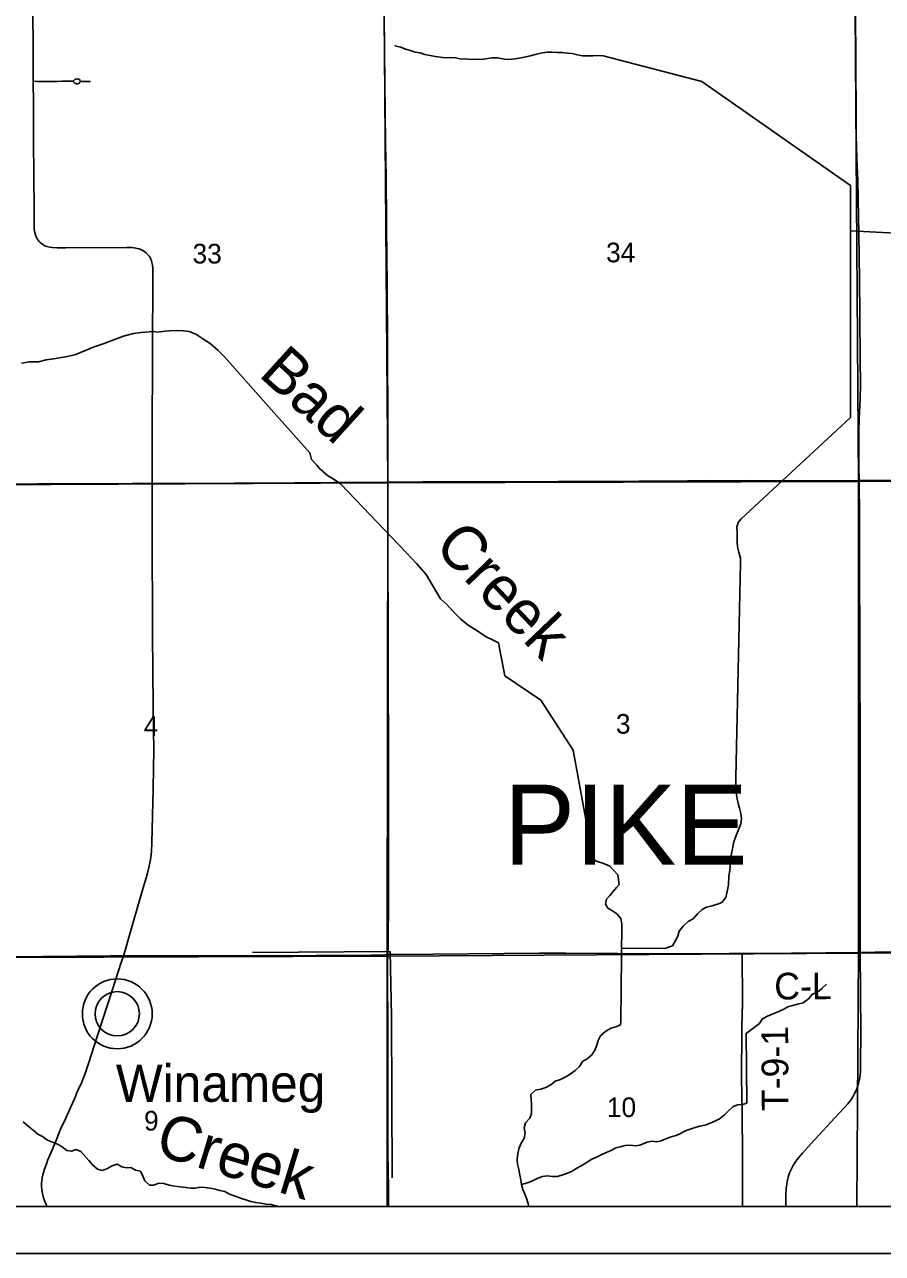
# Model space of a CAD drawing. Extents: x 0 to 34, y 0 to 22.
# Drawn here: x 3.736 to 5.564, y 14 to 16.618 of the extents above; entities that cross this region are included whole.
import ezdxf

# ---------------------------------------------------------------- set-up
doc = ezdxf.new("R2010")
doc.units = 0
for name, color, linetype in [('Default', 7, 'Continuous'), ('GM_X_County_Road', 7, 'Continuous'), ('GM_X_County_Road_Text', 7, 'Continuous'), ('GM_X_Minor_River', 7, 'Continuous'), ('GM_X_Minor_River_Text', 7, 'Continuous'), ('GM_X_Section', 7, 'Continuous'), ('GM_X_Section_Text', 7, 'Continuous'), ('GM_X_State_Route', 7, 'Continuous'), ('GM_X_Township_Road', 7, 'Continuous'), ('GM_X_Township_Road_Text', 7, 'Continuous'), ('GM_X_Township_Text', 7, 'Continuous'), ('GM_X_Unincorporated', 7, 'Continuous'), ('GM_X_Unincorporated_Location', 7, 'Continuous'), ('GM_X_Unincorporated_Text', 7, 'Continuous'), ('SH_Cut_Line', 7, 'Continuous'), ('SH_Data', 7, 'Continuous')]:
    doc.layers.add(name, color=color, linetype=linetype)

msp = doc.modelspace()

# ---------------------------------------------------------------- linework, layer by layer
at = {"layer": 'Default'}
msp.add_lwpolyline([(2.1, 16.6348), (2.1, 14.1), (7.5225, 14.1), (7.5244, 14.8701), (7.5216, 15.6399), (7.5206, 15.6813), (7.5192, 15.8554), (7.5184, 15.927), (7.5171, 16.0545), (7.5165, 16.1851), (7.5145, 16.4463), (7.5138, 16.5271), (7.5134, 16.6254)], dxfattribs=at)
for points in [[(3.5024, 14.1), (4.5087, 14.1), (4.5085, 14.6335), (3.5022, 14.6297)], [(4.5087, 14.1), (5.5091, 14.1), (5.5125, 14.6396), (4.5085, 14.6335)], [(5.5091, 14.1), (6.5139, 14.1), (6.5138, 14.6401), (5.5125, 14.6396)]]:
    msp.add_lwpolyline(points, close=True, dxfattribs=at)
at = {"layer": 'GM_X_County_Road'}
for points in [[(3.7551, 16.4968), (3.7546, 16.5669), (3.7543, 16.6471)], [(3.7637, 16.1607), (3.7614, 16.1652), (3.7595, 16.1697), (3.7581, 16.1751), (3.7572, 16.1819), (3.7568, 16.1939), (3.7567, 16.2342), (3.7564, 16.284), (3.7557, 16.3835), (3.7554, 16.4488), (3.7551, 16.4968)], [(3.7637, 16.1607), (3.7666, 16.1566), (3.7687, 16.1544), (3.7734, 16.1504), (3.7759, 16.1487), (3.7785, 16.1472), (3.7813, 16.146), (3.7842, 16.1451), (3.7901, 16.1437), (3.7963, 16.1429), (3.8056, 16.1423), (3.8243, 16.142), (3.9525, 16.1427), (3.9649, 16.1425), (3.9732, 16.1414), (3.9802, 16.1402), (3.9869, 16.1373), (3.9898, 16.1355), (3.9953, 16.1317)], [(4.0081, 15.6399), (4.0081, 15.6515), (4.0079, 15.6763), (4.008, 15.6981), (4.0084, 15.7229), (4.0082, 15.7416), (4.0096, 16.0896), (4.0095, 16.0989), (4.0089, 16.1051), (4.0077, 16.1112), (4.0068, 16.1142), (4.0057, 16.1171), (4.0038, 16.1214), (4.0016, 16.1247), (3.9953, 16.1317)], [(3.5073, 15.6383), (3.515, 15.6382), (3.5989, 15.6388), (3.6297, 15.6388), (3.6794, 15.639), (3.7261, 15.639), (3.7634, 15.6393), (3.8007, 15.6393), (3.8287, 15.6395), (3.8908, 15.6397), (3.9188, 15.6396), (3.9655, 15.6399), (4.0059, 15.6398), (4.0081, 15.6399)], [(3.9471, 14.6339), (3.95, 14.6431), (3.9671, 14.7028), (3.9872, 14.7714), (3.9976, 14.8072), (4.0014, 14.8223), (4.0039, 14.8346), (4.0052, 14.8438), (4.0065, 14.8562), (4.0075, 14.8749), (4.0106, 14.9899), (4.0114, 15.0334), (4.0115, 15.0738), (4.011, 15.1142), (4.0095, 15.2322), (4.0089, 15.3286), (4.008, 15.5368), (4.0083, 15.5584), (4.0081, 15.5738), (4.0079, 15.6111), (4.0081, 15.6297), (4.0081, 15.6399)], [(4.0081, 15.6399), (4.0276, 15.6402), (4.1053, 15.6404), (4.183, 15.641), (4.3105, 15.6418), (4.3509, 15.6418), (4.3944, 15.6423), (4.4442, 15.6424), (4.5101, 15.6428)], [(4.5101, 15.6428), (4.5841, 15.6433), (4.6742, 15.6436), (4.7147, 15.6438), (4.8732, 15.6446), (4.9354, 15.6447), (5.0442, 15.6452), (5.1002, 15.6453), (5.1966, 15.6463), (5.2401, 15.646), (5.2774, 15.6462), (5.3707, 15.646), (5.4359, 15.6459), (5.4795, 15.6461), (5.5139, 15.6462)], [(5.5139, 15.6462), (5.5634, 15.6462), (5.6256, 15.6465), (5.6629, 15.6464), (5.7531, 15.6465), (5.8526, 15.6468), (5.9178, 15.647), (6.1697, 15.6475), (6.2288, 15.6478), (6.3469, 15.6481), (6.4649, 15.6475), (6.5173, 15.6474)], [(3.5083, 14.6304), (3.5237, 14.6305), (3.531, 14.6306), (3.6305, 14.6314), (3.9195, 14.634), (3.9471, 14.6339)], [(3.7845, 14.1), (3.7824, 14.1044), (3.7788, 14.1129), (3.7768, 14.1187), (3.7752, 14.1247), (3.774, 14.1307), (3.7731, 14.1368), (3.7727, 14.1429), (3.7727, 14.1491), (3.7731, 14.1552), (3.7738, 14.1613), (3.7751, 14.1673), (3.7787, 14.1793), (3.7839, 14.1932), (3.7852, 14.198), (3.7902, 14.209), (3.7963, 14.2223), (3.8046, 14.2429), (3.8146, 14.2681), (3.8206, 14.2803), (3.845, 14.3346), (3.8473, 14.3405), (3.8521, 14.3517), (3.8575, 14.363), (3.8598, 14.3689), (3.8653, 14.3833), (3.8734, 14.4067), (3.8907, 14.4599), (3.9229, 14.5604), (3.9425, 14.6194), (3.9471, 14.6339)], [(3.9471, 14.6339), (4.0283, 14.6336), (4.3578, 14.6345), (4.4448, 14.6349), (4.5039, 14.6364), (4.5103, 14.6365)], [(4.5103, 14.6365), (4.6065, 14.6377), (4.8334, 14.6394), (4.8893, 14.6394), (5.1101, 14.6384), (5.2375, 14.639), (5.2647, 14.639)], [(5.2647, 14.639), (5.2966, 14.6389), (5.5165, 14.641)], [(5.5165, 14.641), (5.548, 14.6414), (5.7625, 14.643), (5.9428, 14.6444), (5.9553, 14.6451), (5.9616, 14.6465), (5.9645, 14.6477), (5.9667, 14.649)]]:
    msp.add_lwpolyline(points, dxfattribs=at)
at = {"layer": 'GM_X_Minor_River'}
for p, q in [((5.2514, 15.013), (5.2615, 15.4713)), ((5.0082, 14.6496), (5.1025, 14.6502))]:
    msp.add_line(p, q, dxfattribs=at)
for points in [[(4.9689, 16.551), (4.9564, 16.5519), (4.9465, 16.5513), (4.9367, 16.5514), (4.9249, 16.5511), (4.9139, 16.5535), (4.9026, 16.5559), (4.8927, 16.5567), (4.8814, 16.558), (4.8708, 16.5585), (4.8598, 16.559), (4.8492, 16.5591), (4.8397, 16.5576), (4.8271, 16.5547), (4.8138, 16.5514), (4.8043, 16.5489), (4.7941, 16.5467), (4.7804, 16.5449), (4.7682, 16.5432), (4.7584, 16.544), (4.7436, 16.5468), (4.7315, 16.5469), (4.7186, 16.5448), (4.7091, 16.5434), (4.6974, 16.5442), (4.6879, 16.5432), (4.6761, 16.5448), (4.6667, 16.5438), (4.6553, 16.5466), (4.6436, 16.5478), (4.6329, 16.5468), (4.6216, 16.5484), (4.6118, 16.55), (4.6, 16.552), (4.5891, 16.554), (4.5789, 16.5572), (4.5686, 16.5588), (4.5581, 16.5627), (4.5479, 16.5654), (4.5381, 16.5697), (4.5275, 16.5717), (4.526, 16.5736)], [(5.2622, 15.5642), (5.4959, 15.7808), (5.4958, 16.2749), (5.1791, 16.4966), (4.9689, 16.551)], [(5.4958, 16.1786), (5.8099, 16.1617), (5.8134, 16.1382), (5.9544, 16.136)], [(3.7302, 15.8965), (3.7462, 15.899), (3.7659, 15.8996), (3.7822, 15.9032), (3.7982, 15.9057), (3.8282, 15.9107), (3.8453, 15.9151), (3.8677, 15.9244), (3.8845, 15.931), (3.9062, 15.938), (3.9241, 15.9455), (3.9473, 15.954), (3.9686, 15.9598), (3.9842, 15.9616), (4.0111, 15.9636), (4.0206, 15.9627), (4.0358, 15.9645), (4.0449, 15.9651), (4.0608, 15.9661), (4.0744, 15.9656), (4.0873, 15.9636), (4.1013, 15.9585), (4.1159, 15.9481), (4.1321, 15.9381), (4.1483, 15.9239), (4.1625, 15.9101), (4.1734, 15.8971), (4.2673, 15.7915), (4.3441, 15.7053), (4.3477, 15.6909), (4.3586, 15.6794), (4.3649, 15.6721), (4.3814, 15.6568), (4.3995, 15.6463), (4.41, 15.6387), (4.5502, 15.4923), (4.5715, 15.4697), (4.5917, 15.446), (4.6226, 15.3945), (4.6354, 15.383), (4.6496, 15.3673), (4.6657, 15.3508), (4.6815, 15.3381), (4.7037, 15.3239), (4.7199, 15.3138), (4.7346, 15.3065), (4.7459, 15.3007), (4.7595, 15.2307), (4.8359, 15.1784), (4.9048, 15.0722), (4.9384, 14.8893), (4.939, 14.8783), (4.9343, 14.8617), (4.9383, 14.8476), (4.9541, 14.8357), (4.9684, 14.8314), (4.9828, 14.8252), (5, 14.8068), (5.0032, 14.7862), (4.997, 14.7795), (4.9828, 14.7622), (4.9759, 14.7543), (4.9739, 14.7437), (4.9787, 14.7356), (4.9885, 14.7295), (4.9976, 14.7237), (5.0062, 14.7134), (5.0087, 14.7023), (5.0067, 14.4933)], [(5.2615, 15.4713), (5.2616, 15.4811), (5.2576, 15.4937), (5.2547, 15.5055), (5.254, 15.5157), (5.2545, 15.5256), (5.2543, 15.5366), (5.2536, 15.5468), (5.256, 15.5567), (5.2622, 15.5642)], [(5.1025, 14.6502), (5.1162, 14.6554), (5.122, 14.6655), (5.1278, 14.6761), (5.131, 14.6867), (5.139, 14.6969), (5.1501, 14.7074), (5.1608, 14.713), (5.1697, 14.7235), (5.1796, 14.7329), (5.1891, 14.7374), (5.2006, 14.7403), (5.212, 14.7443), (5.2215, 14.7477), (5.2299, 14.7582), (5.2323, 14.768), (5.2359, 14.7843), (5.2362, 14.8041), (5.2386, 14.8158), (5.2391, 14.8264), (5.2399, 14.8382), (5.242, 14.8518), (5.2468, 14.8768), (5.2507, 14.887), (5.2562, 14.9006), (5.2617, 14.9154), (5.2633, 14.9256), (5.2619, 14.937), (5.2594, 14.9484), (5.2561, 14.9587), (5.2543, 14.9682), (5.2522, 14.9811), (5.2519, 14.9925), (5.2513, 15.0039), (5.2514, 15.013)], [(4.5182, 14.5049), (4.5148, 14.6431), (4.2218, 14.641)], [(5.3012, 14.4892), (5.3085, 14.4998), (5.3188, 14.5054), (5.3284, 14.5094), (5.3428, 14.5154), (5.3535, 14.5202), (5.3634, 14.5258), (5.3729, 14.5283), (5.3828, 14.5313), (5.3946, 14.5338), (5.4061, 14.5421), (5.4149, 14.5522), (5.4248, 14.5559), (5.4347, 14.5645), (5.4447, 14.5736)], [(4.5192, 14.1609), (4.5182, 14.5049)], [(4.8107, 14.1), (4.8089, 14.1059), (4.8061, 14.1158), (4.8022, 14.1265), (4.7975, 14.1365), (4.7947, 14.1465), (4.7934, 14.1571), (4.791, 14.1667), (4.789, 14.1785), (4.7862, 14.1903), (4.7858, 14.2017), (4.7868, 14.2123), (4.7893, 14.2229), (4.7933, 14.2334), (4.8005, 14.2454), (4.803, 14.2567), (4.8006, 14.2674), (4.8031, 14.278), (4.8128, 14.288), (4.8161, 14.2978), (4.8164, 14.3084), (4.8162, 14.3187), (4.8157, 14.3282), (4.8148, 14.3388), (4.8245, 14.3477), (4.8363, 14.3498), (4.847, 14.3537), (4.857, 14.3592), (4.8667, 14.3669), (4.8778, 14.3705), (4.8877, 14.3752), (4.8982, 14.3822), (4.909, 14.3895), (4.9186, 14.398), (4.925, 14.4085), (4.935, 14.4147), (4.945, 14.4229), (4.951, 14.433), (4.955, 14.4439), (4.9579, 14.4537), (4.9634, 14.4634), (4.9743, 14.4735), (4.9855, 14.4797), (4.9958, 14.4828), (5.0054, 14.4872), (5.0067, 14.4933)], [(5.2746, 14.3202), (5.2732, 14.4687), (5.3018, 14.4901)], [(4.7947, 14.1465), (4.8096, 14.1514), (4.8199, 14.155), (4.8296, 14.1605), (4.8395, 14.1637), (4.8498, 14.165), (4.8611, 14.1636), (4.8714, 14.1637), (4.8828, 14.1673), (4.8928, 14.1708), (4.9031, 14.1755), (4.9128, 14.1818), (4.9231, 14.1872), (4.9347, 14.1946), (4.9443, 14.2008), (4.9543, 14.2051), (4.9647, 14.2098), (4.9754, 14.2153), (4.9857, 14.2189), (4.9957, 14.2247), (5.0053, 14.2272), (5.0156, 14.2296), (5.027, 14.2309), (5.0372, 14.2295), (5.0467, 14.2308), (5.0628, 14.2369), (5.0723, 14.239), (5.0829, 14.238), (5.0925, 14.24), (5.1021, 14.2444), (5.1116, 14.2479), (5.1212, 14.2504), (5.1311, 14.2543), (5.1419, 14.2606), (5.1522, 14.2637), (5.1629, 14.2673), (5.174, 14.2708), (5.1858, 14.2729), (5.1966, 14.2776), (5.2065, 14.2819), (5.2165, 14.2866), (5.2266, 14.2947), (5.2363, 14.3044), (5.246, 14.3129), (5.2559, 14.3165), (5.2666, 14.3174), (5.2746, 14.3202)], [(3.7336, 14.2801), (3.744, 14.2712), (3.7548, 14.2626), (3.7645, 14.254), (3.7746, 14.2492), (3.785, 14.241), (3.7959, 14.237), (3.8065, 14.2326), (3.8166, 14.227), (3.8263, 14.2196), (3.8365, 14.2175), (3.8464, 14.2211), (3.8562, 14.2174), (3.8732, 14.1981), (3.8809, 14.1884), (3.8917, 14.1794), (3.9015, 14.1769)], [(3.9015, 14.1769), (3.9118, 14.1801), (3.923, 14.1867), (3.9337, 14.1899), (3.9434, 14.1847), (3.9536, 14.1826), (3.9631, 14.1828), (3.9729, 14.1776), (3.9831, 14.1755), (3.9885, 14.1648), (3.9928, 14.1544), (4.0025, 14.1455), (4.012, 14.1456), (4.0223, 14.15), (4.0333, 14.1493), (4.0442, 14.1453), (4.0567, 14.1435), (4.0673, 14.1418), (4.0801, 14.1403), (4.0903, 14.139), (4.1002, 14.1388), (4.1101, 14.1408), (4.1203, 14.1406), (4.1317, 14.1388), (4.1426, 14.1371), (4.1524, 14.1338), (4.163, 14.1317), (4.1727, 14.1265), (4.1848, 14.1221), (4.1961, 14.1176), (4.2077, 14.114), (4.2187, 14.1107), (4.2288, 14.1082), (4.2398, 14.1068), (4.2508, 14.1047), (4.2614, 14.1044), (4.2716, 14.1012), (4.2773, 14.1)]]:
    msp.add_lwpolyline(points, dxfattribs=at)
at = {"layer": 'GM_X_Section'}
for points in [[(3.5053, 16.6448), (4.5021, 16.6472), (4.5104, 15.6416), (3.5041, 15.6366)], [(4.5021, 16.6472), (5.5052, 16.6454), (5.5125, 15.6443), (4.5104, 15.6416)], [(5.5052, 16.6454), (6.5111, 16.648), (6.5138, 15.6467), (5.5125, 15.6443)], [(3.5041, 15.6366), (4.5104, 15.6416), (4.5085, 14.6335), (3.5022, 14.6297)], [(4.5104, 15.6416), (5.5125, 15.6443), (5.5125, 14.6396), (4.5085, 14.6335)], [(5.5125, 15.6443), (6.5138, 15.6467), (6.5138, 14.6401), (5.5125, 14.6396)]]:
    msp.add_lwpolyline(points, close=True, dxfattribs=at)
at = {"layer": 'GM_X_State_Route'}
for points in [[(5.5165, 14.641), (5.5164, 14.6659), (5.5164, 14.7343), (5.5163, 14.7903), (5.5161, 15.0701), (5.5158, 15.2783), (5.5152, 15.3467), (5.5149, 15.4151), (5.5144, 15.5675), (5.5139, 15.6462), (5.5136, 15.6763), (5.5131, 15.726), (5.5133, 15.7509), (5.5143, 15.7789), (5.516, 15.8193), (5.5167, 15.8534), (5.5164, 15.9031), (5.5155, 15.9995), (5.5148, 16.0741), (5.5135, 16.1736), (5.5128, 16.2078), (5.5109, 16.2855), (5.509, 16.3321), (5.508, 16.3818), (5.5077, 16.4222), (5.507, 16.5341), (5.5061, 16.6504)], [(5.3577, 14.1), (5.3582, 14.1255), (5.3588, 14.138), (5.3598, 14.1473), (5.3608, 14.1535), (5.363, 14.1626), (5.3659, 14.1716), (5.3697, 14.1802), (5.3742, 14.1884), (5.3794, 14.1962), (5.3851, 14.2037), (5.393, 14.2133), (5.4118, 14.2341), (5.4709, 14.298), (5.4836, 14.3117), (5.4897, 14.3187), (5.4953, 14.3261), (5.5005, 14.3338), (5.5051, 14.3418), (5.5078, 14.3473), (5.5101, 14.353), (5.5129, 14.3618), (5.5149, 14.3708), (5.5161, 14.38), (5.5167, 14.3893), (5.5172, 14.4079), (5.5174, 14.4669), (5.517, 14.5571), (5.5165, 14.641)]]:
    msp.add_lwpolyline(points, dxfattribs=at)
at = {"layer": 'GM_X_Township_Road'}
for points in [[(4.5101, 15.6428), (4.5099, 15.7724), (4.5094, 15.9247), (4.5087, 16.077), (4.5082, 16.1111), (4.5063, 16.2914), (4.5055, 16.3659), (4.503, 16.5586), (4.5024, 16.6295), (4.5021, 16.6469)], [(3.7551, 16.4968), (3.7628, 16.4967), (3.7907, 16.4965), (3.8062, 16.4967), (3.8156, 16.4969), (3.8311, 16.4968), (3.8371, 16.4971), (3.8395, 16.4969)], [(3.8395, 16.4969), (3.8404, 16.498), (3.8418, 16.4992), (3.8435, 16.5006), (3.845, 16.5013), (3.8467, 16.5017), (3.8488, 16.5018), (3.8506, 16.5017), (3.8519, 16.5011), (3.8531, 16.5004), (3.8542, 16.4993), (3.8547, 16.4981), (3.8549, 16.4965)], [(3.8395, 16.4969), (3.8407, 16.4957), (3.8422, 16.4942), (3.8436, 16.4932), (3.8453, 16.4922), (3.8471, 16.4918), (3.849, 16.4918), (3.8513, 16.4922), (3.8536, 16.4933), (3.8543, 16.4942), (3.8548, 16.4953), (3.8549, 16.4965)], [(3.8549, 16.4965), (3.857, 16.4965), (3.8613, 16.4965), (3.8769, 16.4964)], [(4.5103, 14.6365), (4.5108, 14.6535), (4.5113, 14.7592), (4.5116, 14.84), (4.5118, 14.8928), (4.5118, 15.0203), (4.5107, 15.2782), (4.5105, 15.5393), (4.5104, 15.5797), (4.5101, 15.6326), (4.5101, 15.6428)], [(4.5113, 14.1), (4.5114, 14.1376), (4.5104, 14.2153), (4.5102, 14.2774), (4.51, 14.4546), (4.5098, 14.6193), (4.5103, 14.6349), (4.5103, 14.6365)], [(5.2644, 14.4829), (5.265, 14.509), (5.2655, 14.5307), (5.2652, 14.543), (5.2655, 14.5677), (5.2647, 14.6074), (5.2647, 14.6323), (5.2647, 14.639)], [(5.2654, 14.1), (5.2654, 14.1335), (5.2652, 14.208), (5.2647, 14.3011), (5.2636, 14.3756), (5.2642, 14.4749), (5.2644, 14.4829)]]:
    msp.add_lwpolyline(points, dxfattribs=at)
at = {"layer": 'GM_X_Unincorporated'}
for radius in [0.0744, 0.0472]:
    msp.add_circle((3.9339, 14.5104), radius, dxfattribs=at)
at = {"layer": 'GM_X_Unincorporated_Location'}
msp.add_line((3.9339, 14.5104), (3.9339, 14.5104), dxfattribs=at)
at = {"layer": 'SH_Cut_Line'}
msp.add_lwpolyline([(2.1, 20.6957), (2.1, 14.1), (8.9, 14.1), (8.9, 20.8277), (8.6079, 20.8216), (7.476, 20.811), (6.4789, 20.8005), (5.4741, 20.7803), (4.4698, 20.7584), (3.7151, 20.7343), (2.4566, 20.7022)], close=True, dxfattribs=at)
at = {"layer": 'SH_Data'}
for p, q in [((2.1, 14.1), (8.9, 14.1)), ((2, 14), (9, 14))]:
    msp.add_line(p, q, dxfattribs=at)

# ---------------------------------------------------------------- texts
at = {"layer": 'GM_X_County_Road_Text'}
msp.add_text('C-L', height=0.05682, rotation=0.4273, dxfattribs=at).set_placement((5.3333, 14.5408))
at = {"layer": 'GM_X_Minor_River_Text'}
for s, rotation, p in [('Bad', 317.8097, (4.2326, 15.8706)), ('Creek', 313.7065, (4.6058, 15.504)), ('Creek', 343.0229, (4.0111, 14.2119))]:
    msp.add_text(s, height=0.09476, rotation=rotation, dxfattribs=at).set_placement(p)
at = {"layer": 'GM_X_Section_Text'}
for s, height, p in [('33', 0.04186, (4.0942, 16.1088)), ('34', 0.04186, (4.975, 16.1113)), ('4', 0.0419, (3.99, 15.1024)), ('3', 0.0419, (4.9959, 15.1071)), ('10', 0.04186, (4.9767, 14.2905)), ('9', 0.0419, (3.9909, 14.2617))]:
    msp.add_text(s, height=height, rotation=0, dxfattribs=at).set_placement(p)
at = {"layer": 'GM_X_Township_Road_Text'}
msp.add_text('T-9-1', height=0.05682, rotation=90.2917, dxfattribs=at).set_placement((5.3636, 14.3032))
at = {"layer": 'GM_X_Township_Text'}
msp.add_text('PIKE', height=0.17045, rotation=0, dxfattribs=at).set_placement((4.757, 14.8281))
at = {"layer": 'GM_X_Unincorporated_Text'}
msp.add_text('Winameg', height=0.07898, rotation=0, dxfattribs=at).set_placement((3.9309, 14.3229))

doc.saveas('drawing.dxf')
